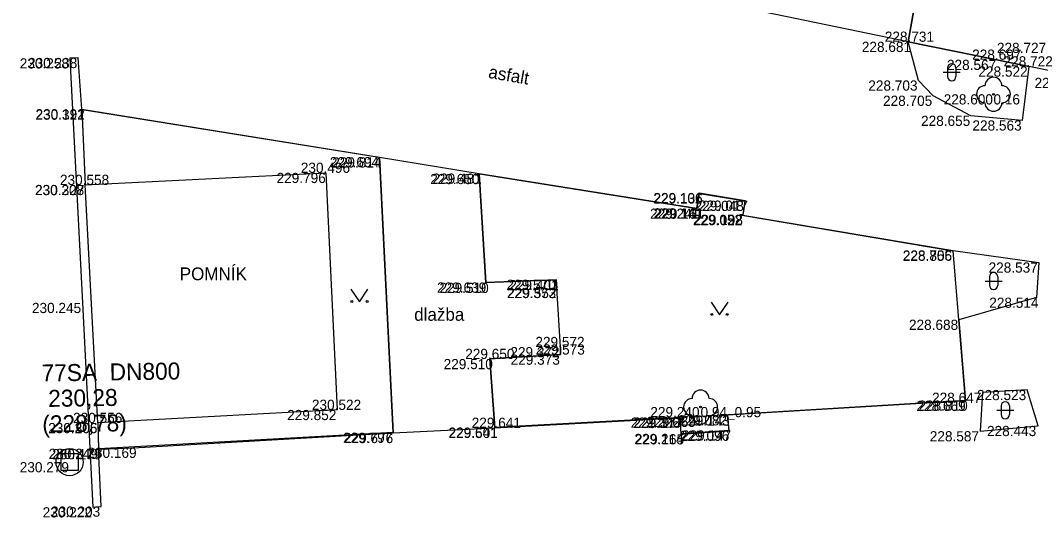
# Model space of a CAD drawing. Extents: x -599516 to -599132, y -1163668 to -1163119.
# Drawn here: x -599435.17 to -599405.11, y -1163172.88 to -1163158.24 of the extents above; entities that cross this region are included whole.
import ezdxf

# ---------------------------------------------------------------- set-up
doc = ezdxf.new("R2010")
doc.units = 0
for name, color, linetype in [('Bod-oznac1', 7, 'Continuous'), ('Bod-oznac2', 7, 'Continuous'), ('Bod-oznac3', 7, 'Continuous'), ('Bod-vyska1', 7, 'Continuous'), ('Bod-vyska2', 7, 'Continuous'), ('Bod-vyska3', 7, 'Continuous'), ('Z_cela-hrobu-dolni-linie', 7, 'Continuous'), ('Z_cela-hrobu-horni-linie', 7, 'Continuous'), ('Z_kanalizace-destova', 7, 'Continuous'), ('Z_kanalizace-znacky-sachta', 7, 'Continuous'), ('Z_komunikace', 7, 'Continuous'), ('Z_kultury-znacky', 7, 'Continuous'), ('Z_nove-stromy-prumer-kmene', 7, 'Continuous'), ('Z_obvod-kmene-spodek-ve-vysce1_2m', 7, 'Continuous'), ('Z_podzemni-obrys-sachty', 7, 'Continuous'), ('Z_popis-budov-povrchu', 7, 'Continuous'), ('Z_povrchy-rozhrani-typu', 7, 'Continuous'), ('Z_stromy-kere', 7, 'Continuous'), ('Z_stromy-nove-vysazene', 7, 'Continuous'), ('Z_vol-lin-obrubnik', 7, 'Continuous'), ('Z_vol-txt-popis-objektu', 7, 'Continuous'), ('Z_zpevnene-plochy', 7, 'Continuous')]:
    doc.layers.add(name, color=color, linetype=linetype)

msp = doc.modelspace()

# ---------------------------------------------------------------- linework, layer by layer
at = {"layer": 'Bod-oznac1'}
for p, q in [((-599409.01, -1163158.872), (-599409.01, -1163158.872)), ((-599433.707, -1163159.358), (-599433.707, -1163159.358)), ((-599433.463, -1163159.347), (-599433.463, -1163159.347)), ((-599406.396, -1163159.401), (-599406.396, -1163159.401)), ((-599405.459, -1163159.598), (-599405.459, -1163159.598)), ((-599408.705, -1163160.01), (-599408.705, -1163160.01)), ((-599408.271, -1163160.458), (-599408.271, -1163160.458)), ((-599406.498, -1163160.417), (-599406.498, -1163160.417)), ((-599433.358, -1163160.855), (-599433.358, -1163160.855)), ((-599433.348, -1163160.867), (-599433.348, -1163160.867)), ((-599407.162, -1163161.048), (-599407.162, -1163161.048)), ((-599405.648, -1163161.185), (-599405.648, -1163161.185)), ((-599424.601, -1163162.273), (-599424.601, -1163162.273)), ((-599424.591, -1163162.264), (-599424.591, -1163162.264)), ((-599426.172, -1163162.73), (-599426.172, -1163162.73)), ((-599421.648, -1163162.75), (-599421.648, -1163162.75)), ((-599421.637, -1163162.762), (-599421.637, -1163162.762)), ((-599433.263, -1163163.086), (-599433.263, -1163163.086)), ((-599433.253, -1163163.086), (-599433.253, -1163163.086)), ((-599415.166, -1163163.322), (-599415.166, -1163163.322)), ((-599415.158, -1163163.333), (-599415.158, -1163163.333)), ((-599413.824, -1163163.553), (-599413.824, -1163163.553)), ((-599413.813, -1163163.545), (-599413.813, -1163163.545)), ((-599415.238, -1163163.782), (-599415.238, -1163163.782)), ((-599415.237, -1163163.772), (-599415.237, -1163163.772)), ((-599415.228, -1163163.782), (-599415.228, -1163163.782)), ((-599413.975, -1163163.966), (-599413.975, -1163163.966)), ((-599413.887, -1163163.962), (-599413.887, -1163163.962)), ((-599413.878, -1163163.972), (-599413.878, -1163163.972)), ((-599407.697, -1163165.021), (-599407.697, -1163165.021)), ((-599407.688, -1163165.012), (-599407.688, -1163165.012)), ((-599405.159, -1163165.367), (-599405.159, -1163165.367)), ((-599421.456, -1163165.967), (-599421.456, -1163165.967)), ((-599421.447, -1163165.957), (-599421.447, -1163165.957)), ((-599419.386, -1163165.885), (-599419.386, -1163165.885)), ((-599419.377, -1163165.875), (-599419.377, -1163165.875)), ((-599419.364, -1163166.117), (-599419.364, -1163166.117)), ((-599419.354, -1163166.116), (-599419.354, -1163166.116)), ((-599433.337, -1163166.557), (-599433.337, -1163166.557)), ((-599405.233, -1163166.403), (-599405.233, -1163166.403)), ((-599407.518, -1163167.052), (-599407.518, -1163167.052)), ((-599419.259, -1163167.858), (-599419.259, -1163167.858)), ((-599419.252, -1163168.079), (-599419.252, -1163168.079)), ((-599421.334, -1163168.209), (-599421.334, -1163168.209)), ((-599406.824, -1163169.2), (-599406.824, -1163169.2)), ((-599405.501, -1163169.12), (-599405.501, -1163169.12)), ((-599407.331, -1163169.432), (-599407.331, -1163169.432)), ((-599407.32, -1163169.441), (-599407.32, -1163169.441)), ((-599425.839, -1163169.708), (-599425.839, -1163169.708)), ((-599415.128, -1163169.623), (-599415.128, -1163169.623)), ((-599414.339, -1163169.874), (-599414.339, -1163169.874)), ((-599414.33, -1163169.864), (-599414.33, -1163169.864)), ((-599432.882, -1163170.093), (-599432.882, -1163170.093)), ((-599432.872, -1163170.093), (-599432.872, -1163170.093)), ((-599415.736, -1163169.933), (-599415.736, -1163169.933)), ((-599415.736, -1163169.943), (-599415.736, -1163169.943)), ((-599415.727, -1163169.933), (-599415.727, -1163169.933)), ((-599415.274, -1163169.911), (-599415.274, -1163169.911)), ((-599405.184, -1163170.179), (-599405.184, -1163170.179)), ((-599424.196, -1163170.377), (-599424.196, -1163170.377)), ((-599424.186, -1163170.386), (-599424.186, -1163170.386)), ((-599421.189, -1163170.226), (-599421.189, -1163170.226)), ((-599421.188, -1163170.236), (-599421.188, -1163170.236)), ((-599415.708, -1163170.424), (-599415.708, -1163170.424)), ((-599415.699, -1163170.413), (-599415.699, -1163170.413)), ((-599414.298, -1163170.31), (-599414.298, -1163170.31)), ((-599414.287, -1163170.319), (-599414.287, -1163170.319)), ((-599406.891, -1163170.334), (-599406.891, -1163170.334)), ((-599432.865, -1163170.862), (-599432.865, -1163170.862)), ((-599432.855, -1163170.851), (-599432.855, -1163170.851)), ((-599431.842, -1163170.82), (-599431.842, -1163170.82)), ((-599433.718, -1163171.245), (-599433.718, -1163171.245)), ((-599433.032, -1163172.573), (-599433.032, -1163172.573)), ((-599432.789, -1163172.552), (-599432.789, -1163172.552))]:
    msp.add_line(p, q, dxfattribs=at)
at = {"layer": 'Bod-oznac2'}
for p, q in [((-599409.01, -1163158.872), (-599409.01, -1163158.872)), ((-599406.396, -1163159.401), (-599406.396, -1163159.401)), ((-599405.459, -1163159.598), (-599405.459, -1163159.598)), ((-599426.172, -1163162.73), (-599426.172, -1163162.73)), ((-599433.263, -1163163.086), (-599433.263, -1163163.086)), ((-599419.259, -1163167.858), (-599419.259, -1163167.858)), ((-599419.252, -1163168.079), (-599419.252, -1163168.079)), ((-599421.334, -1163168.209), (-599421.334, -1163168.209)), ((-599425.839, -1163169.708), (-599425.839, -1163169.708)), ((-599432.882, -1163170.093), (-599432.882, -1163170.093)), ((-599421.188, -1163170.236), (-599421.188, -1163170.236))]:
    msp.add_line(p, q, dxfattribs=at)
at = {"layer": 'Bod-oznac3'}
msp.add_line((-599406.396, -1163159.401), (-599406.396, -1163159.401), dxfattribs=at)
at = {"layer": 'Z_cela-hrobu-dolni-linie'}
msp.add_lwpolyline([(-599405.459, -1163159.598), (-599406.396, -1163159.401), (-599409.01, -1163158.872)], dxfattribs=at)
msp.add_lwpolyline([(-599433.263, -1163163.086), (-599426.172, -1163162.73), (-599425.839, -1163169.708), (-599432.882, -1163170.093)], close=True, dxfattribs=at)
at = {"layer": 'Z_cela-hrobu-horni-linie'}
for points in [[(-599408.456, -1163155.714), (-599409.01, -1163158.872), (-599406.396, -1163159.401), (-599406.396, -1163159.401), (-599405.459, -1163159.598)], [(-599375.883, -1163165.382), (-599376.661, -1163165.219), (-599378.433, -1163164.849), (-599378.433, -1163164.849), (-599383.873, -1163163.775), (-599383.873, -1163163.775), (-599386.472, -1163163.306), (-599386.472, -1163163.306), (-599389.104, -1163162.856), (-599389.104, -1163162.856), (-599391.84, -1163162.348), (-599391.84, -1163162.348), (-599394.388, -1163161.822), (-599394.388, -1163161.822), (-599395.748, -1163161.625), (-599395.748, -1163161.625), (-599397.061, -1163161.343), (-599397.061, -1163161.343), (-599400.974, -1163160.496), (-599400.974, -1163160.496), (-599403.805, -1163159.933), (-599403.805, -1163159.933), (-599405.459, -1163159.598)]]:
    msp.add_lwpolyline(points, dxfattribs=at)
msp.add_lwpolyline([(-599433.263, -1163163.086), (-599426.172, -1163162.73), (-599425.839, -1163169.708), (-599432.882, -1163170.093)], close=True, dxfattribs=at)
at = {"layer": 'Z_kanalizace-znacky-sachta'}
msp.add_lwpolyline([(-599433.968, -1163170.995), (-599433.468, -1163170.995), (-599433.468, -1163171.495), (-599433.968, -1163171.495)], close=True, dxfattribs=at)
at = {"layer": 'Z_komunikace'}
for points in [[(-599408.271, -1163160.458), (-599408.705, -1163160.01), (-599409.01, -1163158.872), (-599408.456, -1163155.714), (-599408.29, -1163154.92), (-599407.508, -1163151.595), (-599404.156, -1163152.194)], [(-599433.358, -1163160.855), (-599433.463, -1163159.347), (-599433.707, -1163159.358), (-599433.337, -1163166.557), (-599433.032, -1163172.573), (-599432.789, -1163172.552), (-599432.865, -1163170.862), (-599431.842, -1163170.82)], [(-599403.805, -1163159.933), (-599405.459, -1163159.598), (-599405.648, -1163161.185), (-599407.162, -1163161.048), (-599408.271, -1163160.458)], [(-599433.358, -1163160.855), (-599424.591, -1163162.264), (-599421.648, -1163162.75), (-599415.237, -1163163.772), (-599415.166, -1163163.322), (-599413.813, -1163163.545), (-599413.878, -1163163.972), (-599407.688, -1163165.012), (-599405.159, -1163165.367), (-599405.233, -1163166.403), (-599407.518, -1163167.052), (-599407.32, -1163169.441), (-599414.33, -1163169.864)], [(-599406.891, -1163170.334), (-599405.184, -1163170.179), (-599405.501, -1163169.12), (-599406.824, -1163169.2), (-599406.891, -1163170.334)], [(-599431.842, -1163170.82), (-599424.186, -1163170.386), (-599421.188, -1163170.236), (-599415.736, -1163169.943), (-599415.708, -1163170.424), (-599414.287, -1163170.319), (-599414.33, -1163169.864)]]:
    msp.add_lwpolyline(points, dxfattribs=at)
at = {"layer": 'Z_kultury-znacky'}
for p, q in [((-599407.853, -1163159.642), (-599407.853, -1163159.892)), ((-599407.603, -1163159.642), (-599407.603, -1163159.892)), ((-599407.978, -1163159.767), (-599407.478, -1163159.767)), ((-599406.744, -1163165.915), (-599406.244, -1163165.915)), ((-599406.619, -1163165.79), (-599406.619, -1163166.04)), ((-599406.369, -1163165.79), (-599406.369, -1163166.04)), ((-599425.429, -1163166.154), (-599425.179, -1163166.529)), ((-599425.179, -1163166.529), (-599424.929, -1163166.154)), ((-599414.819, -1163166.532), (-599414.569, -1163166.907)), ((-599414.569, -1163166.907), (-599414.319, -1163166.532)), ((-599406.399, -1163169.715), (-599405.899, -1163169.715)), ((-599406.274, -1163169.59), (-599406.274, -1163169.84)), ((-599406.024, -1163169.59), (-599406.024, -1163169.84))]:
    msp.add_line(p, q, dxfattribs=at)
for centre in [(-599425.404, -1163166.517), (-599424.954, -1163166.517), (-599414.794, -1163166.895), (-599414.344, -1163166.895)]:
    msp.add_circle(centre, 0.028, dxfattribs=at)
for centre, start, end in [((-599407.729, -1163159.642), 0, 180), ((-599407.729, -1163159.892), 180, 0), ((-599406.494, -1163165.79), 0, 180), ((-599406.494, -1163166.04), 180, 0), ((-599406.149, -1163169.591), 0, 180), ((-599406.149, -1163169.841), 180, 0)]:
    msp.add_arc(centre, 0.125, start, end, dxfattribs=at)
at = {"layer": 'Z_podzemni-obrys-sachty'}
msp.add_circle((-599433.718, -1163171.245), 0.4, dxfattribs=at)
at = {"layer": 'Z_povrchy-rozhrani-typu'}
msp.add_lwpolyline([(-599409.01, -1163158.872), (-599413.527, -1163157.938)], dxfattribs=at)
at = {"layer": 'Z_stromy-kere'}
msp.add_circle((-599415.128, -1163169.623), 0.025, dxfattribs=at)
for centre, start, end in [((-599415.128, -1163169.373), 0, 180), ((-599415.378, -1163169.623), 90, 270), ((-599414.878, -1163169.623), 270, 90), ((-599415.128, -1163169.873), 180, 0)]:
    msp.add_arc(centre, 0.25, start, end, dxfattribs=at)
at = {"layer": 'Z_stromy-nove-vysazene'}
msp.add_circle((-599406.498, -1163160.417), 0.025, dxfattribs=at)
for centre, start, end in [((-599406.498, -1163160.167), 0, 180), ((-599406.748, -1163160.417), 90, 270), ((-599406.248, -1163160.417), 270, 90), ((-599406.498, -1163160.667), 180, 0)]:
    msp.add_arc(centre, 0.25, start, end, dxfattribs=at)
at = {"layer": 'Z_vol-lin-obrubnik'}
for p, q in [((-599433.358, -1163160.855), (-599433.263, -1163163.086)), ((-599432.882, -1163170.093), (-599432.865, -1163170.862))]:
    msp.add_line(p, q, dxfattribs=at)
for points in [[(-599433.253, -1163163.086), (-599433.348, -1163160.867), (-599424.601, -1163162.273), (-599424.196, -1163170.377), (-599432.855, -1163170.851), (-599432.872, -1163170.093)], [(-599419.354, -1163166.116), (-599419.377, -1163165.875), (-599421.447, -1163165.957), (-599421.637, -1163162.762), (-599415.238, -1163163.782), (-599415.228, -1163163.782), (-599415.158, -1163163.333), (-599413.824, -1163163.553), (-599413.887, -1163163.962), (-599413.975, -1163163.966), (-599407.697, -1163165.021), (-599407.331, -1163169.432), (-599415.274, -1163169.911)], [(-599419.259, -1163167.858), (-599419.252, -1163168.079), (-599421.334, -1163168.209), (-599421.188, -1163170.236)], [(-599414.339, -1163169.874), (-599414.298, -1163170.31), (-599415.699, -1163170.413), (-599415.727, -1163169.933), (-599415.736, -1163169.933), (-599421.189, -1163170.226)]]:
    msp.add_lwpolyline(points, dxfattribs=at)
at = {"layer": 'Z_zpevnene-plochy'}
for p, q in [((-599424.591, -1163162.264), (-599424.186, -1163170.386)), ((-599421.456, -1163165.967), (-599421.648, -1163162.75))]:
    msp.add_line(p, q, dxfattribs=at)
msp.add_lwpolyline([(-599421.188, -1163170.236), (-599421.334, -1163168.209), (-599419.252, -1163168.079), (-599419.259, -1163167.858), (-599419.364, -1163166.117), (-599419.386, -1163165.885), (-599421.456, -1163165.967)], dxfattribs=at)

# ---------------------------------------------------------------- texts
at = {"layer": 'Bod-vyska1'}
for s, p in [('228.681', (-599410.376, -1163159.172)), ('230.258', (-599435.187, -1163159.658)), ('230.238', (-599434.943, -1163159.647)), ('228.567', (-599407.868, -1163159.701)), ('228.522', (-599406.941, -1163159.898)), ('228.375', (-599405.288, -1163160.233)), ('228.703', (-599410.186, -1163160.31)), ('228.705', (-599409.752, -1163160.758)), ('228.600', (-599407.964, -1163160.717)), ('230.321', (-599434.724, -1163161.167)), ('230.192', (-599434.722, -1163161.155)), ('228.655', (-599408.632, -1163161.348)), ('228.563', (-599407.118, -1163161.485)), ('229.694', (-599426.05, -1163162.564)), ('229.814', (-599425.979, -1163162.573)), ('229.796', (-599427.621, -1163163.03)), ('229.650', (-599423.094, -1163163.062)), ('229.481', (-599423.026, -1163163.05)), ('230.208', (-599434.741, -1163163.386)), ('230.327', (-599434.734, -1163163.386)), ('229.106', (-599416.519, -1163163.622)), ('229.136', (-599416.513, -1163163.633)), ('229.048', (-599415.304, -1163163.853)), ('229.017', (-599415.179, -1163163.845)), ('229.241', (-599416.616, -1163164.082)), ('229.141', (-599416.511, -1163164.072)), ('229.161', (-599416.479, -1163164.082)), ('229.052', (-599415.355, -1163164.262)), ('229.022', (-599415.346, -1163164.272)), ('229.198', (-599415.33, -1163164.266)), ('228.705', (-599409.169, -1163165.312)), ('228.856', (-599409.167, -1163165.321)), ('228.537', (-599406.642, -1163165.667)), ('229.639', (-599422.894, -1163166.257)), ('229.510', (-599422.82, -1163166.267)), ('229.570', (-599420.847, -1163166.175)), ('229.401', (-599420.762, -1163166.185)), ('229.373', (-599420.836, -1163166.417)), ('229.552', (-599420.824, -1163166.416)), ('230.245', (-599434.828, -1163166.857)), ('228.514', (-599406.622, -1163166.703)), ('228.688', (-599408.988, -1163167.352)), ('229.372', (-599420.731, -1163168.158)), ('229.373', (-599420.724, -1163168.379)), ('229.510', (-599422.698, -1163168.509)), ('228.647', (-599408.307, -1163169.5)), ('228.523', (-599406.983, -1163169.42)), ('228.669', (-599408.767, -1163169.741)), ('228.810', (-599408.707, -1163169.732)), ('229.852', (-599427.309, -1163170.008)), ('229.240', (-599416.608, -1163169.923)), ('229.082', (-599415.798, -1163170.164)), ('229.143', (-599415.717, -1163170.174)), ('230.305', (-599434.35, -1163170.393)), ('230.206', (-599434.348, -1163170.393)), ('229.226', (-599417.186, -1163170.233)), ('229.177', (-599417.106, -1163170.243)), ('229.317', (-599417.104, -1163170.233)), ('229.269', (-599416.721, -1163170.211)), ('228.443', (-599406.688, -1163170.479)), ('229.797', (-599425.659, -1163170.677)), ('229.676', (-599425.635, -1163170.686)), ('229.641', (-599422.555, -1163170.526)), ('229.501', (-599422.552, -1163170.536)), ('229.214', (-599417.077, -1163170.713)), ('229.165', (-599417.063, -1163170.724)), ('229.096', (-599415.733, -1163170.619)), ('229.147', (-599415.677, -1163170.61)), ('228.587', (-599408.374, -1163170.634)), ('230.249', (-599434.335, -1163171.151)), ('230.179', (-599434.231, -1163171.162)), ('230.169', (-599433.195, -1163171.12)), ('230.279', (-599435.188, -1163171.545)), ('230.222', (-599434.512, -1163172.873)), ('230.203', (-599434.267, -1163172.852))]:
    msp.add_text(s, height=0.3, dxfattribs=at).set_placement(p)
at = {"layer": 'Bod-vyska2'}
for s, p in [('228.731', (-599409.7, -1163158.872)), ('228.697', (-599407.126, -1163159.401)), ('228.722', (-599406.201, -1163159.598)), ('230.496', (-599426.906, -1163162.73)), ('230.558', (-599434.003, -1163163.086)), ('229.572', (-599419.995, -1163167.858)), ('229.573', (-599419.988, -1163168.079)), ('229.650', (-599422.062, -1163168.209)), ('230.522', (-599426.579, -1163169.708)), ('230.556', (-599433.616, -1163170.093)), ('229.641', (-599421.871, -1163170.236))]:
    msp.add_text(s, height=0.3, dxfattribs=at).set_placement(p)
at = {"layer": 'Bod-vyska3'}
msp.add_text('228.727', height=0.3, dxfattribs=at).set_placement((-599406.396, -1163159.201))
at = {"layer": 'Z_kanalizace-destova'}
for s, p in [('77SA  DN800   ', (-599434.542, -1163168.873)), (' 230,28', (-599434.531, -1163169.623)), ('(228,78) ', (-599434.519, -1163170.373))]:
    msp.add_text(s, height=0.5, rotation=0.8872, dxfattribs=at).set_placement(p)
at = {"layer": 'Z_nove-stromy-prumer-kmene'}
msp.add_text('0.16', height=0.3, dxfattribs=at).set_placement((-599406.498, -1163160.717))
at = {"layer": 'Z_obvod-kmene-spodek-ve-vysce1_2m'}
msp.add_text('0.94_0.95', height=0.3, dxfattribs=at).set_placement((-599415.128, -1163169.923))
at = {"layer": 'Z_popis-budov-povrchu'}
msp.add_text('asfalt', height=0.375, rotation=350.2145, dxfattribs=at).set_placement((-599421.399, -1163159.932))
msp.add_text('dlažba', height=0.375, dxfattribs=at).set_placement((-599423.566, -1163167.084))
at = {"layer": 'Z_vol-txt-popis-objektu'}
msp.add_text('POMNÍK', height=0.375, dxfattribs=at).set_placement((-599430.473, -1163165.89))

doc.saveas('drawing.dxf')
